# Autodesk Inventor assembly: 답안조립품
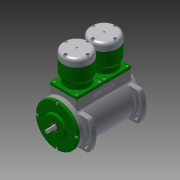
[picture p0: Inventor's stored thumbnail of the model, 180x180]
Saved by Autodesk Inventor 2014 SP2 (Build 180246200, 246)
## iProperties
Created: 2017-08
Part Number: 답안조립품
Document SubType Name: Assembly
Designer: 거성
Mass: 7431.61 g
Surface Area: 5102.67 cm^2
Volume: 2063.48 cm^3
Density: 3.6015 g/cm^3
Author: 거성
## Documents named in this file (16)
- C:\Users\거성\Desktop\370808V1019\답안조립품.iam
- C:\Users\거성\Desktop\370808V1019\본체.ipt
- C:\Users\거성\Desktop\370808V1019\앞커버.ipt
- C:\Users\거성\Desktop\370808V1019\오일 실 12 25 7.ipt
- C:\Users\거성\Desktop\370808V1019\베어링 12 x 28 x 8.ipt
- C:\Users\거성\Desktop\370808V1019\크랭크축.ipt
- C:\Users\거성\Desktop\370808V1019\커넥팅로드.ipt
- C:\Users\거성\Desktop\370808V1019\커넥팅로드 엔드.ipt
- C:\Users\거성\Desktop\370808V1019\너트 M4.ipt
- C:\Users\거성\Desktop\370808V1019\육각 머리 볼트 M4 x 16.ipt
- C:\Users\거성\Desktop\370808V1019\피스톤.ipt
- C:\Users\거성\Desktop\370808V1019\피스톤핀.ipt
- C:\Users\거성\Desktop\370808V1019\실린더.ipt
- C:\Users\거성\Desktop\370808V1019\볼트 M4 x 8.ipt
- C:\Users\거성\Desktop\370808V1019\실린더헤드.ipt
- C:\Users\거성\Desktop\370808V1019\볼트 M5 x 20.ipt
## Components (4 placed, 2 different names)
1. 피스톤:1
2. 피스톤핀:1
3. 피스톤:2
4. 피스톤핀:2
